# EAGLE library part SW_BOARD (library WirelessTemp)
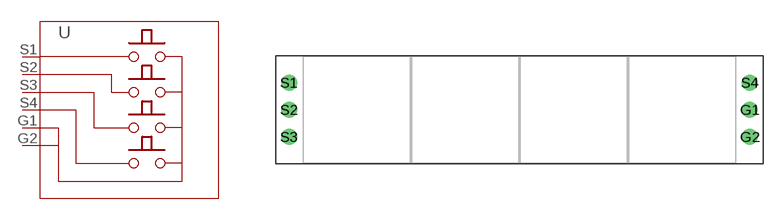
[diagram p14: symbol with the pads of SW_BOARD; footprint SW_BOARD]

Designator prefix -

## SW_BOARD  [SW_BOARD]
G1  G1  pas
G2  G2  pas
S1  S1  pas
S2  S2  pas
S3  S3  pas
S4  S4  pas

## Footprint SW_BOARD (pad centres in mm)
drill 1 round: G1 21.59,0; G2 21.59,-2.54; S1 -21.59,2.54; S2 -21.59,0; S3 -21.59,-2.54; S4 21.59,2.54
